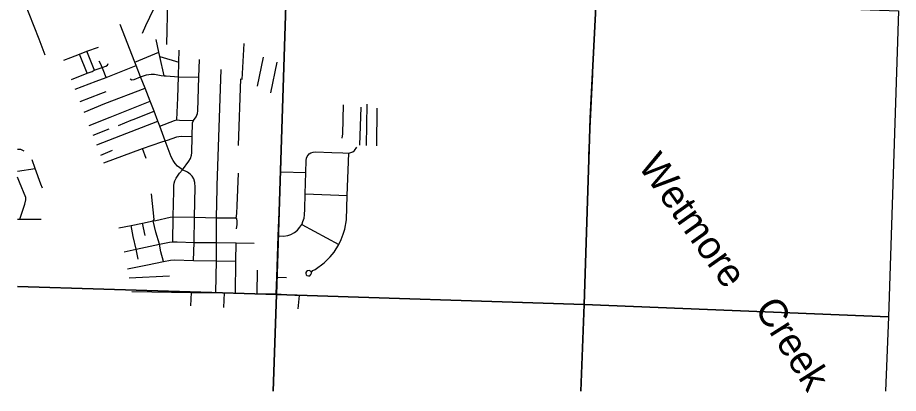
# Model space of a CAD drawing. Extents: x 25.6 to 80.6, y 0.2 to 24.5.
# Drawn here: x 25.639 to 28.606, y 21.122 to 22.388 of the extents above; entities that cross this region are included whole.
import ezdxf

# ---------------------------------------------------------------- set-up
doc = ezdxf.new("R2010")
doc.units = 0
for name, color, linetype in [('GM_X_City_Street', 7, 'Continuous'), ('GM_X_Minor_River_Text', 7, 'Continuous'), ('GM_X_Section', 7, 'Continuous')]:
    doc.layers.add(name, color=color, linetype=linetype)

msp = doc.modelspace()

# ---------------------------------------------------------------- linework, layer by layer
at = {"layer": 'GM_X_City_Street'}
for p, q in [((26.395, 22.1798), (26.4023, 22.3002)), ((25.8731, 22.2005), (25.8477, 22.2645)), ((26.0334, 22.2378), (26.1146, 22.2709)), ((26.1177, 22.2565), (26.1821, 22.2372)), ((26.4471, 22.1565), (26.467, 22.2546)), ((26.4925, 22.1345), (26.5137, 22.2373)), ((26.3118, 21.8226), (26.3242, 22.213)), ((26.3832, 21.9572), (26.3905, 22.1819)), ((27.5636, 21.9245), (27.5769, 22.1968)), ((26.7916, 21.9584), (26.7959, 22.0866)), ((26.8141, 21.9573), (26.817, 22.0961)), ((26.8488, 21.9557), (26.8499, 22.0825)), ((25.9784, 22.0247), (26.0217, 22.0423)), ((25.8935, 21.9914), (25.9477, 22.0127)), ((25.9188, 21.9249), (25.9586, 21.941)), ((26.0721, 21.9137), (26.0598, 21.9469)), ((25.6389, 21.8712), (25.6984, 21.8795)), ((25.6455, 21.8337), (25.6389, 21.8502)), ((26.5255, 21.8683), (26.6099, 21.8658)), ((26.6073, 21.7946), (26.7498, 21.7889)), ((25.6389, 21.7094), (25.6461, 21.7095)), ((25.6461, 21.7095), (25.7182, 21.7089)), ((26.0691, 21.6545), (26.0595, 21.6959)), ((26.5964, 21.6911), (26.721, 21.6238)), ((26.0152, 21.5119), (26.1507, 21.5183)), ((26.4458, 21.458), (26.4473, 21.5377)), ((26.5119, 21.5141), (26.5443, 21.5129)), ((26.223, 21.4169), (26.2253, 21.4622)), ((26.3341, 21.4112), (26.3357, 21.4607)), ((26.5873, 21.4521), (26.5829, 21.4066))]:
    msp.add_line(p, q, dxfattribs=at)
for points in [[(26.1418, 22.2976), (26.145, 22.4432), (26.1453, 22.477), (26.1446, 22.4813)], [(25.7319, 22.2608), (25.7112, 22.3155), (25.6611, 22.4427), (25.6596, 22.4464)], [(26.0602, 22.3354), (26.0707, 22.3609), (26.0976, 22.4177), (26.1032, 22.4276), (26.1053, 22.4332), (26.1064, 22.4384), (26.1062, 22.4444), (26.1053, 22.4496)], [(26.038, 22.2263), (26.0334, 22.2378), (25.984, 22.3647)], [(25.7952, 22.2442), (25.8182, 22.2532), (25.8477, 22.2645), (25.8725, 22.2743), (25.9111, 22.2877)], [(26.1322, 22.1919), (26.1177, 22.2565), (26.1146, 22.2709), (26.1058, 22.3143)], [(25.897, 22.2102), (25.8972, 22.2134), (25.8725, 22.2743)], [(26.1752, 22.043), (26.1782, 22.1174), (26.1806, 22.1888), (26.1821, 22.2372), (26.1831, 22.2784)], [(25.8206, 22.1796), (25.8731, 22.2005), (25.8901, 22.2064), (25.897, 22.2102), (25.9233, 22.2196), (25.9365, 22.2243), (25.9417, 22.2274), (25.9439, 22.2327)], [(25.9375, 22.1865), (25.9276, 22.2114), (25.9233, 22.2196), (25.9191, 22.2312), (25.9135, 22.2412)], [(26.165, 21.8222), (26.1662, 21.8301), (26.1687, 21.8383), (26.1728, 21.8474), (26.1849, 21.8642), (26.1948, 21.8756), (26.216, 21.9043), (26.221, 21.9137), (26.2243, 21.924), (26.2257, 21.932), (26.2274, 21.9873), (26.2284, 22.0331), (26.2317, 22.0416), (26.2404, 22.0536), (26.2449, 22.065), (26.2462, 22.0738), (26.2493, 22.1876), (26.2518, 22.2465)], [(25.8332, 22.1468), (25.9033, 22.1735), (25.9375, 22.1865), (26.038, 22.2263)], [(26.2317, 21.5702), (26.2333, 21.6307), (26.2349, 21.7156), (26.2369, 21.8168), (26.2363, 21.8325), (26.2327, 21.8444), (26.2275, 21.8539), (26.2207, 21.8609), (26.2108, 21.8674), (26.1948, 21.8756), (26.1855, 21.8815), (26.1778, 21.888), (26.1697, 21.8967), (26.1629, 21.9064), (26.1568, 21.9185), (26.1364, 21.9732), (26.1176, 22.0225), (26.1113, 22.0395), (26.0986, 22.0729), (26.086, 22.1059), (26.0683, 22.1505), (26.053, 22.1881), (26.038, 22.2263)], [(26.053, 22.1881), (26.0737, 22.1948), (26.0885, 22.1972), (26.0999, 22.1969), (26.1225, 22.1925), (26.1322, 22.1919), (26.1399, 22.1913), (26.1806, 22.1888), (26.2493, 22.1876)], [(26.0186, 22.1819), (26.0232, 22.1785), (26.0314, 22.1788), (26.053, 22.1881)], [(25.8497, 22.1047), (25.9193, 22.1318), (25.9378, 22.1388)], [(25.863, 22.0694), (25.9328, 22.098), (26.0683, 22.1505)], [(26.5102, 21.4575), (26.5119, 21.5141), (26.5165, 21.6524), (26.5255, 21.8683), (26.5321, 22.1161)], [(25.8805, 22.0245), (25.9506, 22.0522), (26.086, 22.1059)], [(26.7325, 21.9819), (26.735, 21.9969), (26.7368, 22.0936)], [(26.0217, 22.0423), (26.0282, 22.0449), (26.0986, 22.0729)], [(25.9058, 21.9593), (25.9866, 21.9911), (26.1113, 22.0395)], [(26.1176, 22.0225), (26.1679, 22.041), (26.1752, 22.043), (26.1844, 22.0428), (26.2317, 22.0416)], [(25.929, 21.8985), (26.0598, 21.9469), (26.1252, 21.9697), (26.1364, 21.9732), (26.144, 21.9745), (26.1749, 21.986), (26.1819, 21.9875), (26.1927, 21.988), (26.2274, 21.9873)], [(25.6389, 21.9448), (25.6483, 21.945), (25.6595, 21.9392)], [(26.6275, 21.5319), (26.6255, 21.5344), (26.6217, 21.5362), (26.6153, 21.5352), (26.6119, 21.5327), (26.6103, 21.5295), (26.6102, 21.5258), (26.6112, 21.5221), (26.6138, 21.5192), (26.6187, 21.5178), (26.6231, 21.5187), (26.6274, 21.5224), (26.6288, 21.527), (26.6288, 21.5311), (26.6338, 21.5357), (26.6411, 21.5396), (26.6722, 21.5624), (26.6921, 21.5821), (26.7049, 21.5984), (26.721, 21.6238), (26.7296, 21.6405), (26.7362, 21.658), (26.7412, 21.6758), (26.7465, 21.7073), (26.7498, 21.7889), (26.7546, 21.9312)], [(26.6208, 21.9288), (26.6266, 21.9322), (26.6344, 21.9349), (26.6428, 21.9358), (26.6974, 21.934), (26.7345, 21.9329), (26.7546, 21.9312), (26.7585, 21.932), (26.7682, 21.9357), (26.7739, 21.9403), (26.7817, 21.951)], [(25.7232, 21.8132), (25.7168, 21.8266), (25.6984, 21.8795), (25.6874, 21.9089)], [(26.5971, 21.6928), (26.6004, 21.7006), (26.604, 21.7129), (26.6053, 21.724), (26.6061, 21.7425), (26.6073, 21.7946), (26.6099, 21.8658), (26.6112, 21.9065), (26.6123, 21.9146), (26.6141, 21.9205), (26.6208, 21.9288)], [(26.3765, 21.6761), (26.3785, 21.6909), (26.3785, 21.7028), (26.377, 21.7102), (26.3749, 21.7138), (26.3764, 21.7193), (26.3776, 21.7294), (26.3782, 21.7542), (26.3826, 21.8639)], [(25.6665, 21.7739), (25.6661, 21.782), (25.6455, 21.8337)], [(26.1631, 21.7225), (26.164, 21.7561), (26.1647, 21.8074), (26.1649, 21.8212), (26.165, 21.8222)], [(26.3091, 21.6323), (26.3094, 21.714), (26.3115, 21.8136), (26.3118, 21.8226)], [(26.1303, 21.5664), (26.1218, 21.5995), (26.1165, 21.6245), (26.1047, 21.6658), (26.0961, 21.7034), (26.0995, 21.7084), (26.0898, 21.7939)], [(25.6461, 21.7095), (25.6636, 21.7597), (25.6665, 21.7739)], [(26.1614, 21.6332), (26.1629, 21.7166), (26.1631, 21.7225)], [(25.9805, 21.6793), (26.0218, 21.6879), (26.0595, 21.6959), (26.0961, 21.7034), (26.1045, 21.7044), (26.1534, 21.7152), (26.1629, 21.7166), (26.2349, 21.7156), (26.3094, 21.714), (26.367, 21.7132), (26.3749, 21.7138)], [(26.5165, 21.6524), (26.5344, 21.652), (26.5489, 21.6539), (26.5593, 21.6573), (26.5714, 21.6642), (26.5818, 21.6722), (26.5902, 21.6824), (26.5964, 21.6911), (26.5971, 21.6928)], [(26.045, 21.5742), (26.0384, 21.6082), (26.0286, 21.6501), (26.0218, 21.6879)], [(25.9975, 21.5992), (26.0384, 21.6082), (26.1165, 21.6245), (26.1505, 21.6313), (26.1614, 21.6332), (26.1767, 21.6329), (26.2333, 21.6307), (26.3091, 21.6303), (26.3754, 21.629), (26.4361, 21.6283)], [(26.3063, 21.4619), (26.3089, 21.5684), (26.3091, 21.6303), (26.3091, 21.6323)], [(26.3727, 21.4601), (26.3742, 21.5673), (26.3754, 21.629)], [(26.0093, 21.5413), (26.0763, 21.5552), (26.1303, 21.5664), (26.1538, 21.5714), (26.1673, 21.5725), (26.2317, 21.5702), (26.3089, 21.5684), (26.3742, 21.5673)], [(26.0238, 21.4658), (26.2253, 21.4622), (26.3063, 21.4619), (26.3357, 21.4607), (26.3727, 21.4601), (26.4458, 21.458), (26.5102, 21.4575), (26.5125, 21.4574), (26.5873, 21.4521)]]:
    msp.add_lwpolyline(points, dxfattribs=at)
at = {"layer": 'GM_X_Section'}
for points in [[(25.6389, 22.4898), (26.544, 22.4659), (26.5116, 21.4558), (25.6389, 21.4823)], [(25.6389, 21.4823), (26.5116, 21.4558), (26.5004, 21.1303)], [(26.5004, 21.1303), (26.5116, 21.4558), (27.548, 21.4221), (27.5364, 21.1303)], [(27.5364, 21.1303), (27.548, 21.4221), (28.5734, 21.3807), (28.5629, 21.1303)]]:
    msp.add_lwpolyline(points, dxfattribs=at)
for points in [[(26.544, 22.4659), (27.5882, 22.4479), (27.5679, 22.0496), (27.548, 21.4221), (26.5116, 21.4558)], [(28.6064, 22.4106), (28.5734, 21.3807), (27.548, 21.4221), (27.5679, 22.0496), (27.5882, 22.4479)]]:
    msp.add_lwpolyline(points, close=True, dxfattribs=at)

# ---------------------------------------------------------------- texts
at = {"layer": 'GM_X_Minor_River_Text'}
for s, rotation, p in [('Wetmore', 305.3622, (27.7268, 21.8884)), ('Creek', 302.313, (28.12, 21.4081))]:
    msp.add_text(s, height=0.09472, rotation=rotation, dxfattribs=at).set_placement(p)

doc.saveas('drawing.dxf')
